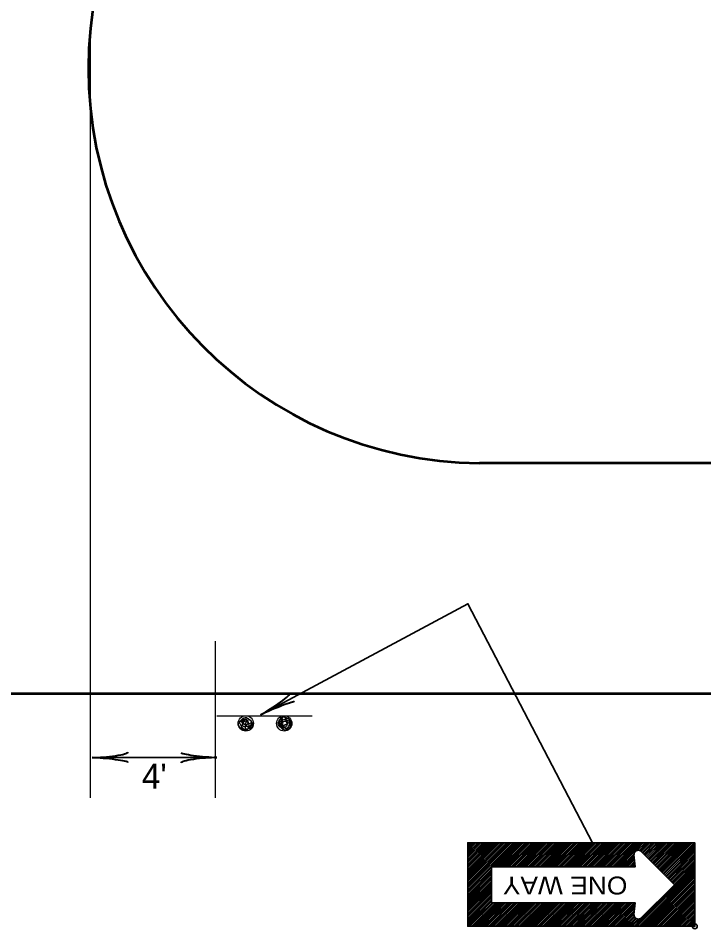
# Model space of a CAD drawing. Extents: x -133 to 547, y -328 to 112.
# Drawn here: x 53.5 to 108.6, y -137.5 to -64.2 of the extents above; entities that cross this region are included whole.
import ezdxf
from ezdxf.enums import TextEntityAlignment as Align

# ---------------------------------------------------------------- set-up
doc = ezdxf.new("R2010")
doc.units = 0
doc.header["$LTSCALE"] = 0.8
doc.header["$PDMODE"] = 32
doc.header["$PDSIZE"] = 0.4
doc.layers.add('1', color=7, linetype='Continuous', lineweight=35)
doc.layers.add('4', color=7, linetype='Continuous', lineweight=25)

msp = doc.modelspace()

# ---------------------------------------------------------------- linework, layer by layer
at = {"layer": '1', "lineweight": 25}
for p, q in [((59.3016, -126.9336), (59.3016, -64.8886)), ((69.319, -126.9336), (69.319, -114.3288)), ((77.0934, -120.3438), (69.4434, -120.3438))]:
    msp.add_line(p, q, dxfattribs=at)
at = {"layer": '1', "lineweight": 53}
for p, q in [((195.534, -100.0198), (90.534, -100.0198)), ((-87.7097, -118.5198), (195.534, -118.5198))]:
    msp.add_line(p, q, dxfattribs=at)
at = {"layer": '1'}
for p, q in [((59.4193, -123.6807), (69.4368, -123.6807)), ((93.3745, -130.5312), (89.5945, -134.3113)), ((93.2345, -130.5312), (89.5945, -134.1712)), ((93.0945, -130.5312), (89.5945, -134.0312)), ((92.9745, -130.5312), (89.5945, -133.8912)), ((92.8345, -130.5312), (89.5945, -133.7713)), ((92.6945, -130.5312), (89.5945, -133.6312)), ((92.5545, -130.5312), (89.5945, -133.4913)), ((92.4345, -130.5312), (89.5945, -133.3512)), ((92.2945, -130.5312), (89.5945, -133.2113)), ((92.1545, -130.5312), (89.5945, -133.0913)), ((92.0145, -130.5312), (89.5945, -132.9512)), ((91.8745, -130.5312), (89.5945, -132.8113)), ((91.7545, -130.5312), (89.5945, -132.6712)), ((91.6145, -130.5312), (89.5945, -132.5312)), ((91.4745, -130.5312), (89.5945, -132.4112)), ((91.3345, -130.5312), (89.5945, -132.2713)), ((91.1945, -130.5312), (89.5945, -132.1312)), ((91.0745, -130.5312), (89.5945, -131.9913)), ((90.9345, -130.5312), (89.5945, -131.8713)), ((90.7945, -130.5312), (89.5945, -131.7312)), ((90.6545, -130.5312), (89.5945, -131.5913)), ((90.5345, -130.5312), (89.5945, -131.4512)), ((90.3945, -130.5312), (89.5945, -131.3113)), ((90.2545, -130.5312), (89.5945, -131.1912)), ((90.1145, -130.5312), (89.5945, -131.0512)), ((89.9745, -130.5312), (89.5945, -130.9112)), ((89.8545, -130.5312), (89.5945, -130.7713)), ((89.7145, -130.5312), (89.5945, -130.6312)), ((93.5145, -130.5312), (91.5745, -132.4712)), ((93.6545, -130.5312), (91.7145, -132.4712)), ((93.7745, -130.5312), (91.8545, -132.4712)), ((93.9145, -130.5312), (91.9745, -132.4712)), ((94.0545, -130.5312), (92.1145, -132.4712)), ((94.1945, -130.5312), (92.2545, -132.4712)), ((94.3345, -130.5312), (92.3945, -132.4712)), ((94.4545, -130.5312), (92.5145, -132.4712)), ((94.5945, -130.5312), (92.6545, -132.4712)), ((94.7345, -130.5312), (92.7945, -132.4712)), ((94.8745, -130.5312), (92.9345, -132.4712)), ((95.0145, -130.5312), (93.0745, -132.4712)), ((95.1345, -130.5312), (93.1945, -132.4712)), ((95.2745, -130.5312), (93.3345, -132.4712)), ((95.4145, -130.5312), (93.4745, -132.4712)), ((95.5545, -130.5312), (93.6145, -132.4712)), ((95.6745, -130.5312), (93.7545, -132.4712)), ((95.8145, -130.5312), (93.8745, -132.4712)), ((95.9545, -130.5312), (94.0145, -132.4712)), ((96.0945, -130.5312), (94.1545, -132.4712)), ((96.2345, -130.5312), (94.2945, -132.4712)), ((96.3545, -130.5312), (94.4345, -132.4712)), ((96.4945, -130.5312), (94.5545, -132.4712)), ((96.6345, -130.5312), (94.6945, -132.4712)), ((96.7745, -130.5312), (94.8345, -132.4712)), ((96.9145, -130.5312), (94.9745, -132.4712)), ((97.0345, -130.5312), (95.0945, -132.4712)), ((97.1745, -130.5312), (95.2345, -132.4712)), ((97.3145, -130.5312), (95.3745, -132.4712)), ((97.4545, -130.5312), (95.5145, -132.4712)), ((97.5745, -130.5312), (95.6545, -132.4712)), ((97.7145, -130.5312), (95.7745, -132.4712)), ((97.8545, -130.5312), (95.9145, -132.4712)), ((97.9945, -130.5312), (96.0545, -132.4712)), ((98.1345, -130.5312), (96.1945, -132.4712)), ((98.2545, -130.5312), (96.3345, -132.4712)), ((98.3945, -130.5312), (96.4545, -132.4712)), ((98.5345, -130.5312), (96.5945, -132.4712)), ((98.6745, -130.5312), (96.7345, -132.4712)), ((98.8145, -130.5312), (96.8745, -132.4712)), ((98.9345, -130.5312), (96.9945, -132.4712)), ((99.0745, -130.5312), (97.1345, -132.4712)), ((99.2145, -130.5312), (97.2745, -132.4712)), ((99.3545, -130.5312), (97.4145, -132.4712)), ((99.4945, -130.5312), (97.5545, -132.4712)), ((99.6145, -130.5312), (97.6745, -132.4712)), ((99.7545, -130.5312), (97.8145, -132.4712)), ((99.8945, -130.5312), (97.9545, -132.4712)), ((100.0345, -130.5312), (98.0945, -132.4712)), ((100.1545, -130.5312), (98.2345, -132.4712)), ((100.2945, -130.5312), (98.3545, -132.4712)), ((100.4345, -130.5312), (98.4945, -132.4712)), ((100.5745, -130.5312), (98.6345, -132.4712)), ((100.7145, -130.5312), (98.7745, -132.4712)), ((100.8345, -130.5312), (98.9145, -132.4712)), ((100.9745, -130.5312), (99.0345, -132.4712)), ((101.1145, -130.5312), (99.1745, -132.4712)), ((101.2545, -130.5312), (99.3145, -132.4712)), ((101.3945, -130.5312), (99.4545, -132.4712)), ((101.5145, -130.5312), (99.5745, -132.4712)), ((101.6545, -130.5312), (99.7145, -132.4712)), ((101.7945, -130.5312), (99.8545, -132.4712)), ((101.9345, -130.5312), (99.9945, -132.4712)), ((102.0745, -130.5312), (100.1345, -132.4712)), ((102.1945, -130.5312), (100.2545, -132.4712)), ((102.3345, -130.5312), (100.3945, -132.4712)), ((102.4745, -130.5312), (100.5345, -132.4712)), ((102.6145, -130.5312), (100.6745, -132.4712)), ((102.7345, -130.5312), (100.8145, -132.4712)), ((102.8745, -130.5312), (100.9345, -132.4712)), ((103.0145, -130.5312), (101.0745, -132.4712)), ((103.1545, -130.5312), (101.2145, -132.4712)), ((103.2945, -130.5312), (101.3545, -132.4712)), ((103.4145, -130.5312), (101.4945, -132.4712)), ((103.5545, -130.5312), (101.6145, -132.4712)), ((103.6945, -130.5312), (101.7545, -132.4712)), ((103.8345, -130.5312), (103.2145, -131.1513)), ((103.9745, -130.5312), (103.3545, -131.1513)), ((104.0945, -130.5312), (103.4545, -131.1712)), ((104.2345, -130.5312), (103.5145, -131.2312)), ((104.3745, -130.5312), (103.5945, -131.3113)), ((104.5145, -130.5312), (103.6545, -131.3713)), ((104.6345, -130.5312), (103.7345, -131.4512)), ((104.7745, -130.5312), (103.7945, -131.5112)), ((104.9145, -130.5312), (103.8545, -131.5712)), ((105.0545, -130.5312), (103.9345, -131.6513)), ((105.1945, -130.5312), (103.9945, -131.7113)), ((105.3145, -130.5312), (104.0745, -131.7912)), ((105.4545, -130.5312), (104.1345, -131.8512)), ((105.5945, -130.5312), (104.1945, -131.9112)), ((105.7345, -130.5312), (104.2745, -131.9913)), ((105.8745, -130.5312), (104.3345, -132.0512)), ((105.9945, -130.5312), (104.4145, -132.1312)), ((106.1345, -130.5312), (104.4745, -132.1912)), ((106.2745, -130.5312), (104.5345, -132.2512)), ((106.4145, -130.5312), (104.6145, -132.3312)), ((106.5545, -130.5312), (104.6745, -132.3912)), ((106.6745, -130.5312), (104.7545, -132.4712)), ((106.8145, -130.5312), (104.8145, -132.5312)), ((106.9545, -130.5312), (104.8745, -132.5913)), ((107.0945, -130.5312), (104.9545, -132.6712)), ((107.2145, -130.5312), (105.0145, -132.7312)), ((107.3545, -130.5312), (105.0945, -132.7912)), ((107.4945, -130.5312), (105.1545, -132.8713)), ((107.6345, -130.5312), (105.2145, -132.9313)), ((107.7745, -130.5312), (105.2945, -133.0112)), ((107.8345, -130.5913), (105.3545, -133.0712)), ((107.8345, -130.7312), (105.4345, -133.1312)), ((107.8345, -130.8713), (105.4945, -133.2113)), ((107.8345, -130.9913), (105.5545, -133.2713)), ((102.9545, -131.4112), (101.8945, -132.4712)), ((102.9545, -131.5512), (102.0345, -132.4712)), ((102.9545, -131.6712), (102.1545, -132.4712)), ((102.9745, -131.7912), (102.2945, -132.4712)), ((103.4745, -131.1912), (106.1945, -133.9112)), ((107.8345, -131.1312), (105.6345, -133.3512)), ((107.8345, -131.2713), (105.6945, -133.4112)), ((107.8345, -131.4112), (105.7545, -133.4712)), ((107.8345, -131.5512), (105.8345, -133.5512)), ((107.8345, -131.6712), (105.8945, -133.6112)), ((102.9745, -131.9112), (102.4345, -132.4712)), ((102.9945, -132.0512), (102.5745, -132.4712)), ((102.9945, -132.1712), (102.7145, -132.4712)), ((103.0145, -132.2912), (102.8345, -132.4712)), ((107.8345, -132.3512), (102.9545, -137.2512)), ((103.0145, -132.4112), (102.9745, -132.4712)), ((107.8345, -132.4913), (103.0745, -137.2512)), ((107.8345, -131.8113), (105.9745, -133.6912)), ((107.8345, -131.9512), (106.0345, -133.7512)), ((107.8345, -132.0913), (106.0945, -133.8113)), ((107.8345, -132.2312), (106.1745, -133.8912)), ((91.5145, -132.5312), (89.5945, -134.4512)), ((91.5145, -132.6712), (89.5945, -134.5712)), ((91.5145, -132.8113), (89.5945, -134.7113)), ((91.5145, -132.9313), (89.5945, -134.8512)), ((91.5145, -133.0712), (89.5945, -134.9913)), ((91.5145, -133.2113), (89.5945, -135.1112)), ((107.8345, -132.6312), (103.2145, -137.2512)), ((107.8345, -132.7713), (103.3545, -137.2512)), ((107.8345, -132.8912), (103.4945, -137.2512)), ((107.8345, -133.0312), (103.6345, -137.2512)), ((107.8345, -133.1712), (103.7545, -137.2512)), ((91.5145, -133.3512), (89.5945, -135.2512)), ((91.5145, -133.4712), (89.5945, -135.3912)), ((91.5145, -133.6112), (89.5945, -135.5312)), ((91.5145, -133.7512), (89.5945, -135.6712)), ((91.5145, -133.8912), (89.5945, -135.7912)), ((106.1945, -133.9112), (103.4745, -136.6112)), ((107.8345, -133.3113), (103.8945, -137.2512)), ((107.8345, -133.4512), (104.0345, -137.2512)), ((107.8345, -133.5712), (104.1745, -137.2512)), ((107.8345, -133.7113), (104.3145, -137.2512)), ((107.8345, -133.8512), (104.4345, -137.2512)), ((91.5145, -134.0312), (89.5945, -135.9313)), ((91.5145, -134.1513), (89.5945, -136.0712)), ((91.5145, -134.2912), (89.5945, -136.2113)), ((91.5145, -134.4313), (89.5945, -136.3512)), ((91.5145, -134.5712), (89.5945, -136.4712)), ((91.5145, -134.7113), (89.5945, -136.6112)), ((107.8345, -133.9913), (104.5745, -137.2512)), ((107.8345, -134.1312), (104.7145, -137.2512)), ((107.8345, -134.2512), (104.8545, -137.2512)), ((107.8345, -134.3912), (104.9745, -137.2512)), ((107.8345, -134.5312), (105.1145, -137.2512)), ((107.8345, -134.6712), (105.2545, -137.2512)), ((91.5145, -134.8312), (89.5945, -136.7512)), ((91.5145, -134.9712), (89.5945, -136.8912)), ((91.5145, -135.1112), (89.5945, -137.0312)), ((91.5145, -135.2512), (89.5945, -137.1513)), ((91.5545, -135.3512), (89.6345, -137.2512)), ((91.6745, -135.3512), (89.7745, -137.2512)), ((91.8145, -135.3512), (89.9145, -137.2512)), ((91.9545, -135.3512), (90.0545, -137.2512)), ((92.0945, -135.3512), (90.1945, -137.2512)), ((92.2145, -135.3512), (90.3145, -137.2512)), ((92.3545, -135.3512), (90.4545, -137.2512)), ((92.4945, -135.3512), (90.5945, -137.2512)), ((92.6345, -135.3512), (90.7345, -137.2512)), ((92.7745, -135.3512), (90.8545, -137.2512)), ((92.8945, -135.3512), (90.9945, -137.2512)), ((93.0345, -135.3512), (91.1345, -137.2512)), ((93.1745, -135.3512), (91.2745, -137.2512)), ((93.3145, -135.3512), (91.4145, -137.2512)), ((93.4545, -135.3512), (91.5345, -137.2512)), ((93.5745, -135.3512), (91.6745, -137.2512)), ((93.7145, -135.3512), (91.8145, -137.2512)), ((93.8545, -135.3512), (91.9545, -137.2512)), ((93.9945, -135.3512), (92.0945, -137.2512)), ((94.1145, -135.3512), (92.2145, -137.2512)), ((94.2545, -135.3512), (92.3545, -137.2512)), ((94.3945, -135.3512), (92.4945, -137.2512)), ((94.5345, -135.3512), (92.6345, -137.2512)), ((94.6745, -135.3512), (92.7745, -137.2512)), ((94.7945, -135.3512), (92.8945, -137.2512)), ((94.9345, -135.3512), (93.0345, -137.2512)), ((95.0745, -135.3512), (93.1745, -137.2512)), ((95.2145, -135.3512), (93.3145, -137.2512)), ((95.3545, -135.3512), (93.4345, -137.2512)), ((95.4745, -135.3512), (93.5745, -137.2512)), ((95.6145, -135.3512), (93.7145, -137.2512)), ((95.7545, -135.3512), (93.8545, -137.2512)), ((95.8945, -135.3512), (93.9945, -137.2512)), ((96.0345, -135.3512), (94.1145, -137.2512)), ((96.1545, -135.3512), (94.2545, -137.2512)), ((96.2945, -135.3512), (94.3945, -137.2512)), ((96.4345, -135.3512), (94.5345, -137.2512)), ((96.5745, -135.3512), (94.6745, -137.2512)), ((96.6945, -135.3512), (94.7945, -137.2512)), ((96.8345, -135.3512), (94.9345, -137.2512)), ((96.9745, -135.3512), (95.0745, -137.2512)), ((97.1145, -135.3512), (95.2145, -137.2512)), ((97.2545, -135.3512), (95.3545, -137.2512)), ((97.3745, -135.3512), (95.4745, -137.2512)), ((97.5145, -135.3512), (95.6145, -137.2512)), ((97.6545, -135.3512), (95.7545, -137.2512)), ((97.7945, -135.3512), (95.8945, -137.2512)), ((97.9345, -135.3512), (96.0145, -137.2512)), ((98.0545, -135.3512), (96.1545, -137.2512)), ((98.1945, -135.3512), (96.2945, -137.2512)), ((98.3345, -135.3512), (96.4345, -137.2512)), ((98.4745, -135.3512), (96.5745, -137.2512)), ((98.6145, -135.3512), (96.6945, -137.2512)), ((98.7345, -135.3512), (96.8345, -137.2512)), ((98.8745, -135.3512), (96.9745, -137.2512)), ((99.0145, -135.3512), (97.1145, -137.2512)), ((99.1545, -135.3512), (97.2545, -137.2512)), ((99.2745, -135.3512), (97.3745, -137.2512)), ((99.4145, -135.3512), (97.5145, -137.2512)), ((99.5545, -135.3512), (97.6545, -137.2512)), ((99.6945, -135.3512), (97.7945, -137.2512)), ((99.8345, -135.3512), (97.9145, -137.2512)), ((99.9545, -135.3512), (98.0545, -137.2512)), ((100.0945, -135.3512), (98.1945, -137.2512)), ((100.2345, -135.3512), (98.3345, -137.2512)), ((100.3745, -135.3512), (98.4745, -137.2512)), ((100.5145, -135.3512), (98.5945, -137.2512)), ((100.6345, -135.3512), (98.7345, -137.2512)), ((100.7745, -135.3512), (98.8745, -137.2512)), ((100.9145, -135.3512), (99.0145, -137.2512)), ((101.0545, -135.3512), (99.1545, -137.2512)), ((101.1745, -135.3512), (99.2745, -137.2512)), ((101.3145, -135.3512), (99.4145, -137.2512)), ((101.4545, -135.3512), (99.5545, -137.2512)), ((101.5945, -135.3512), (99.6945, -137.2512)), ((101.7345, -135.3512), (99.8345, -137.2512)), ((101.8545, -135.3512), (99.9545, -137.2512)), ((101.9945, -135.3512), (100.0945, -137.2512)), ((102.1345, -135.3512), (100.2345, -137.2512)), ((102.2745, -135.3512), (100.3745, -137.2512)), ((102.4145, -135.3512), (100.4945, -137.2512)), ((102.5345, -135.3512), (100.6345, -137.2512)), ((102.6745, -135.3512), (100.7745, -137.2512)), ((102.8145, -135.3512), (100.9145, -137.2512)), ((102.9545, -135.3512), (101.0545, -137.2512)), ((103.0145, -135.4112), (101.1745, -137.2512)), ((107.8345, -134.8113), (105.3945, -137.2512)), ((107.8345, -134.9313), (105.5345, -137.2512)), ((107.8345, -135.0712), (105.6545, -137.2512)), ((107.8345, -135.2113), (105.7945, -137.2512)), ((107.8345, -135.3512), (105.9345, -137.2512)), ((103.0145, -135.5512), (101.3145, -137.2512)), ((102.9945, -135.7113), (101.4545, -137.2512)), ((102.9745, -135.8512), (101.5945, -137.2512)), ((102.9745, -136.0112), (101.7345, -137.2512)), ((102.9545, -136.1513), (101.8545, -137.2512)), ((107.8345, -135.4712), (106.0745, -137.2512)), ((107.8345, -135.6112), (106.2145, -137.2512)), ((107.8345, -135.7512), (106.3345, -137.2512)), ((107.8345, -135.8912), (106.4745, -137.2512)), ((107.8345, -136.0312), (106.6145, -137.2512)), ((107.8345, -136.1513), (106.7545, -137.2512)), ((102.9345, -136.2912), (101.9945, -137.2512)), ((102.9545, -136.4313), (102.1345, -137.2512)), ((102.9945, -136.5112), (102.2745, -137.2512)), ((103.0745, -136.5913), (102.3945, -137.2512)), ((103.1545, -136.6312), (102.5345, -137.2512)), ((103.2545, -136.6712), (102.6745, -137.2512)), ((103.4145, -136.6513), (102.8145, -137.2512)), ((107.8345, -136.2912), (106.8945, -137.2512)), ((107.8345, -136.4313), (107.0145, -137.2512)), ((107.8345, -136.5712), (107.1545, -137.2512)), ((107.8345, -136.7113), (107.2945, -137.2512)), ((107.8345, -136.8312), (107.4345, -137.2512)), ((107.8345, -136.9712), (107.5545, -137.2512)), ((107.8345, -137.1112), (107.6945, -137.2512))]:
    msp.add_line(p, q, dxfattribs=at)
for points in [[(72.9676, -120.2374), (89.6052, -111.3214), (99.6278, -130.5312)], [(102.9345, -136.2912), (103.0345, -135.3512), (91.5145, -135.3512), (91.5145, -132.4712), (103.0345, -132.4712), (102.9345, -131.5112)]]:
    msp.add_lwpolyline(points, dxfattribs=at)
msp.add_lwpolyline([(107.8345, -137.2512), (89.5945, -137.2512), (89.5945, -130.5312), (107.8345, -130.5312)], close=True, dxfattribs=at)
at = {"layer": '1', "lineweight": 53}
msp.add_arc((90.8728, -68.2698), 31.7518, 90.61145, 269.38854, dxfattribs=at)
at = {"layer": '1'}
for centre, start, end in [((103.2922, -131.4873), 58.76645, 183.36449), ((103.2922, -136.3209), 176.63551, 301.23355)]:
    msp.add_arc(centre, 0.3492, start, end, dxfattribs=at)
at = {"layer": '1', "lineweight": 40}
for centre, major_axis, ratio, start_param, end_param in [((73.7989, -119.4785), (-1.5002, -0.9811), 0.122415, 0.8963533, 3.1415927), ((74.0552, -119.8947), (-1.6311, -0.6748), 0.07063, 3.1407148, 5.41811), ((60.5398, -123.8923), (-1.7565, 0.1757), 0.07063, 3.1407148, 5.41811), ((60.5105, -123.4044), (-1.7857, -0.1562), 0.122415, 0.8963533, 3.1415927), ((68.3456, -123.957), (1.7857, 0.1562), 0.122415, 0.8963533, 3.1415927), ((68.3162, -123.4691), (1.7565, -0.1757), 0.07063, 3.1407148, 5.41811)]:
    msp.add_ellipse(centre, major_axis=major_axis, ratio=ratio, start_param=start_param, end_param=end_param, dxfattribs=at)
at = {"layer": '1', "lineweight": 25}
for points in [[(71.8134, -120.4637), (72.1134, -120.6737), (72.2634, -120.9737), (72.1734, -121.1837), (71.8434, -121.3937), (71.5134, -121.3937), (71.1834, -121.0637), (71.3934, -120.6737), (71.8134, -120.4637), (71.9934, -120.5837), (72.1434, -120.6737), (72.2034, -120.9437), (71.9934, -121.3037), (71.8734, -121.4537), (71.4534, -121.2137), (71.5134, -120.9137), (71.5734, -120.7338), (71.6934, -120.6737), (71.8734, -120.6737), (71.9634, -120.8537), (71.9934, -121.1837), (71.7834, -121.1837), (71.6334, -121.2137), (71.5134, -121.0337), (71.7234, -120.7638), (71.9034, -120.8837), (71.9334, -121.0037), (71.7234, -121.0337), (71.7534, -121.0938), (71.3034, -120.7638), (71.6934, -121.4838), (71.7834, -121.0637), (72.0534, -121.3337), (72.3534, -120.9137), (71.7234, -121.0337), (71.8434, -120.6437), (71.4234, -120.7338), (71.7234, -121.0337)], [(74.8434, -120.4038), (75.1734, -120.5537), (75.3834, -120.8837), (75.3234, -121.2437), (74.9334, -121.4838), (74.5734, -121.2737), (74.3634, -120.9737), (74.4234, -120.7638), (74.8434, -120.4038), (75.0534, -120.6437), (75.2334, -120.7338), (75.2634, -120.9137), (75.0534, -121.3337), (74.8434, -121.3037), (74.6934, -121.1837), (74.4534, -121.0337), (74.6334, -120.6737), (74.8734, -120.6137), (75.0234, -120.7338), (75.1134, -120.9137), (75.0534, -121.0938), (74.9934, -121.2137), (74.6934, -121.1238), (74.7534, -120.9137), (74.7534, -120.7938), (74.9934, -120.7938), (75.0534, -120.9737), (74.7234, -121.0938), (74.6634, -121.0637), (74.3934, -120.7938), (74.7834, -121.3637), (74.6934, -121.0938), (75.1434, -121.3937), (75.3534, -120.8837), (74.7234, -121.0938), (74.6934, -120.5537), (74.6034, -120.6737), (74.7234, -121.0938)]]:
    msp.add_spline(points, degree=3, dxfattribs=at)
at = {"layer": '1'}
msp.add_point((107.8345, -137.2512), dxfattribs=at)
at = {"layer": '4'}
for centre in [(71.7652, -120.9342), (74.8504, -120.9339)]:
    msp.add_circle(centre, 0.615, dxfattribs=at)

# ---------------------------------------------------------------- texts
at = {"layer": '1'}
msp.add_text("4'", height=2, dxfattribs=at).set_placement((63.4134, -126.1746))
at = {"layer": '1', "width": 1.1}
msp.add_text('ONE WAY', height=1.44, rotation=180, dxfattribs=at).set_placement((97.4142, -133.2512), align=Align.CENTER)

doc.saveas('drawing.dxf')
